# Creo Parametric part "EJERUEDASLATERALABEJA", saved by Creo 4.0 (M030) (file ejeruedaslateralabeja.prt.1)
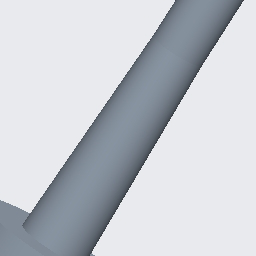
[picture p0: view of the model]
Units: millimeter Newton Second (mmNs); MM, TONNE, SECS

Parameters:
  MODELED_BY = "AJ"

Created from: MMNS_PART_SOLID.PRT

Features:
  1. datum plane "RIGHT"
  2. datum plane "TOP"
  3. datum plane "FRONT"
  4. coordinate system
  5. extrusion "Extrude 1"
  6. extrusion "Extrude 2"
  7. extrusion "Extrude 3"

Surfaces: 3 plane, 2 cylinder, 1 cone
